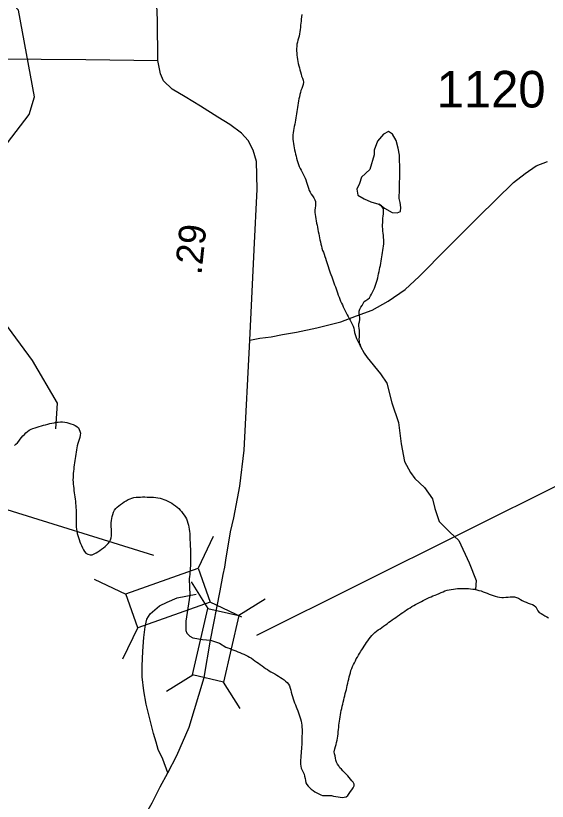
# Model space of a CAD drawing. Extents: x 1950930 to 2061844, y 904556 to 1017002.
# Drawn here: x 1995566 to 1998037, y 913449 to 917098 of the extents above; entities that cross this region are included whole.
import ezdxf

# ---------------------------------------------------------------- set-up
doc = ezdxf.new("R2010")
doc.units = 0
for name, color, linetype in [('Exist Hydrographic Creek Single Shore', 7, 'Continuous'), ('Exist Hydrographic Misc Water Feature', 7, 'Continuous'), ('Exist Road Primary US Structure Standard Bridge CELL', 7, 'Continuous'), ('Exist Road Secondary Structure Standard Bridge CELL', 7, 'Continuous'), ('Exist Road Secondary Structure Standard Bridge Number Label', 7, 'Continuous'), ('Exist Road Secondary Type 51 Attributed', 7, 'Continuous'), ('Exist Road Secondary Type 51 Number Label', 7, 'Continuous')]:
    doc.layers.add(name, color=color, linetype=linetype)

msp = doc.modelspace()

# ---------------------------------------------------------------- linework, layer by layer
at = {"layer": 'Exist Hydrographic Creek Single Shore'}
for points in [[(1995560.5, 915100.6), (1995567.5, 915106.8), (1995574.7, 915114.2), (1995581, 915122.2), (1995587, 915130.2), (1995593.5, 915138.2), (1995600.3, 915145.7), (1995606.7, 915152.9), (1995613.8, 915160.3), (1995621.2, 915166.4), (1995629.4, 915172.1), (1995638.2, 915176.9), (1995646.8, 915180.8), (1995656.7, 915183.7), (1995666.5, 915186.7), (1995676.2, 915190.1), (1995686.2, 915192.3), (1995695.6, 915195.3), (1995705.3, 915197.5), (1995715.3, 915200.9), (1995725, 915203), (1995734.6, 915205.2), (1995744.9, 915207.3), (1995754.9, 915209.1), (1995764.5, 915210.4), (1995774.4, 915210.9), (1995784, 915210.7), (1995794.1, 915209.6), (1995803.9, 915207.6), (1995813.8, 915205), (1995823.4, 915201.9), (1995833, 915198.4), (1995842.1, 915194.5), (1995850.7, 915189.6), (1995858.7, 915183.9)], [(1995858.7, 915183.9), (1995865.2, 915167.9), (1995867.3, 915159), (1995866, 915149.1), (1995864, 915139.2), (1995861.1, 915129.6), (1995858.3, 915119.9), (1995855.2, 915110.1), (1995852.7, 915100), (1995850.7, 915090.5), (1995849, 915080.7), (1995847.4, 915070.8), (1995845.7, 915060.9), (1995844.1, 915051), (1995842.5, 915041.4), (1995840.8, 915031.6), (1995839.6, 915021.6), (1995838, 915011.7), (1995837.1, 915001.3), (1995835.9, 914991.4), (1995834.7, 914981.4), (1995833.9, 914971.8), (1995833, 914961.8), (1995832.8, 914952), (1995832.4, 914942.4), (1995832.8, 914931.7), (1995833.6, 914921.5), (1995834.7, 914912), (1995835.9, 914902.1), (1995837.1, 914892.2), (1995838.6, 914882.2), (1995840.2, 914872.2), (1995841.6, 914862.6), (1995842.9, 914852.7), (1995843.9, 914842.8), (1995844.7, 914832.2), (1995845.5, 914822.2), (1995846, 914812.5), (1995847, 914802.6), (1995847.4, 914792.8), (1995847.4, 914782.7), (1995848, 914772.8), (1995847.8, 914762.3), (1995847.6, 914752.6), (1995847.2, 914742.5), (1995846.8, 914732.8), (1995847.6, 914722.2), (1995848.4, 914712.2), (1995850.3, 914703.1), (1995852.5, 914693.4), (1995855.6, 914683.2), (1995858, 914673.5), (1995861.3, 914664.4), (1995864.8, 914654.6), (1995868.3, 914645.5), (1995872, 914636.5), (1995876.3, 914626.5), (1995881, 914617.2), (1995886.3, 914608.7), (1995892.9, 914602), (1995902.3, 914597), (1995912.4, 914593.8), (1995922.2, 914593.9), (1995931, 914598.2), (1995939.9, 914603), (1995948.3, 914607.8), (1995956.9, 914613.4), (1995965.5, 914619.3), (1995973.9, 914625.8), (1995981.7, 914632.4), (1995989.1, 914638.5), (1995995.8, 914646), (1996002.4, 914654), (1996007.3, 914663), (1996010.6, 914672.6), (1996012, 914681.7), (1996012.5, 914691.8), (1996011.6, 914702.5), (1996011.2, 914712.3), (1996010, 914723), (1996010.4, 914732.7), (1996010.6, 914742.4), (1996011.4, 914752.4), (1996012.9, 914762.4), (1996014.7, 914771.8), (1996017.2, 914781.5), (1996020.7, 914791.6), (1996025.2, 914801.4), (1996031.5, 914808.6), (1996038.5, 914814.9), (1996046.5, 914821.4), (1996054.3, 914827.9), (1996062.5, 914833.9), (1996071.1, 914840), (1996079.7, 914845.1), (1996088.5, 914849.9), (1996097.8, 914853.7), (1996106.8, 914857.3), (1996116, 914859.1), (1996126.3, 914861.6)], [(1996126.3, 914861.6), (1996136.1, 914862.1), (1996146.1, 914861.8), (1996156.6, 914862.6), (1996166.7, 914862.3), (1996176.9, 914862), (1996186.5, 914861.8), (1996197.2, 914861.8), (1996207.3, 914860.7), (1996217.3, 914859.6), (1996227.3, 914858.8), (1996237.2, 914856.9), (1996246.8, 914854.2), (1996255.6, 914850.4), (1996264.9, 914847), (1996273.9, 914842.8), (1996283.3, 914837.7), (1996291.7, 914832.8), (1996300.1, 914827.5), (1996308.5, 914821.7), (1996316.3, 914814.9), (1996324.3, 914808.4), (1996331.3, 914801.6), (1996337.7, 914794.6), (1996344, 914786.2), (1996349.8, 914778.1), (1996355.1, 914769.1), (1996359.6, 914760), (1996363.5, 914750.9), (1996367, 914741), (1996369.7, 914731.7), (1996371.9, 914722), (1996373.3, 914712.8), (1996374.6, 914702.1), (1996375.4, 914692.2), (1996376, 914682.4), (1996376.2, 914671.8), (1996376.4, 914662.1), (1996376.8, 914652.2), (1996377.2, 914642), (1996377.9, 914632.3), (1996378.5, 914621.6), (1996378.7, 914611.7), (1996378.7, 914602), (1996379.1, 914592.3), (1996379.5, 914581.6), (1996379.5, 914571.5), (1996379.7, 914561.7), (1996379.3, 914552.1), (1996378.9, 914541.9), (1996378.1, 914532.3), (1996377.7, 914521.4), (1996376.4, 914511.9), (1996375.2, 914501.9), (1996374, 914492.4), (1996372.7, 914482.5), (1996375.1, 914405.5), (1996357.7, 914285.5), (1996357.7, 914242.9), (1996362.4, 914230.3), (1996376.6, 914216.1), (1996389.3, 914208.2), (1996435, 914200.3), (1996471.8, 914196.7), (1996513.9, 914182.9), (1996543.5, 914165.5)], [(1997333, 914303.1), (1997341.6, 914308.8), (1997349.8, 914314.4), (1997357.6, 914321), (1997366.2, 914326.5), (1997374.8, 914332.2), (1997383, 914337.4), (1997391.4, 914342.2), (1997399.6, 914347.8), (1997408, 914353.5), (1997416.6, 914358.3), (1997425.5, 914363), (1997433.9, 914367.8), (1997443.1, 914372.5), (1997452.1, 914377.3), (1997460.9, 914382), (1997469.8, 914386.7), (1997479, 914390.6), (1997487.8, 914395.3), (1997497.4, 914399.1), (1997506.1, 914403.1), (1997515.7, 914406.9), (1997524.7, 914410), (1997534.3, 914414.3), (1997543.4, 914418.1), (1997552.6, 914422), (1997561.6, 914425.9), (1997571.5, 914428.8), (1997581.3, 914431), (1997590.9, 914432.4), (1997601, 914434.2), (1997610.8, 914435.5), (1997620.5, 914436.8), (1997630.7, 914437.4), (1997641, 914437.4), (1997650.6, 914437.1), (1997661.1, 914437.6), (1997671.1, 914436.8), (1997680.6, 914435.8), (1997690.6, 914434.7), (1997700.6, 914433.6), (1997704.3, 914432.6)], [(1997704.3, 914432.6), (1997710.5, 914430.9), (1997719.7, 914428.2), (1997729.6, 914425.6), (1997739.2, 914422.1), (1997748.4, 914418.6), (1997757.9, 914415.1), (1997767.5, 914411.6), (1997776.7, 914408.2), (1997785.9, 914404.7), (1997795.6, 914401.3), (1997805.4, 914398.6), (1997814.9, 914396.8), (1997825.3, 914395.6), (1997834.5, 914395.4), (1997844.8, 914396.2), (1997855.3, 914396.8), (1997865.1, 914398.1), (1997875.6, 914398.9), (1997885.2, 914397.9), (1997895, 914395.9), (1997903.6, 914391.8), (1997912.7, 914386.8), (1997921.1, 914381.5), (1997929.9, 914376.5), (1997939.1, 914373), (1997948.8, 914369.5), (1997958.4, 914366), (1997968, 914362.5), (1997976.6, 914358.4), (1997984, 914351.5), (1997988.5, 914342.4), (1997993.3, 914333.1), (1998000.2, 914326.4), (1998008.2, 914320.7), (1998016.8, 914315.8), (1998025.7, 914310.3), (1998034.5, 914305.3), (1998043.7, 914301.1)], [(1997074.4, 913468), (1997084.5, 913466.8), (1997093.9, 913467.5), (1997102.3, 913469.8), (1997109.7, 913476), (1997116.5, 913485.1), (1997122.2, 913494), (1997128.8, 913502.7), (1997135.7, 913511.7), (1997140.2, 913520.5), (1997139.4, 913528.7), (1997134.9, 913537.1), (1997129.6, 913544.4), (1997123.4, 913552.2), (1997116.5, 913559.7), (1997109.7, 913567.3), (1997102.5, 913574.9), (1997094.7, 913582.1), (1997087.5, 913589.8), (1997080.4, 913597.4), (1997073.4, 913604.8), (1997067.7, 913613), (1997062.3, 913621.6), (1997058, 913629.9), (1997055.1, 913639.7), (1997052.9, 913649.3), (1997050.6, 913659.5), (1997049, 913669.4), (1997046.3, 913679.2), (1997050.4, 913693.2), (1997053.3, 913702.9), (1997055.8, 913712.7), (1997058.2, 913722.4), (1997060.3, 913732.3), (1997061.9, 913742.1), (1997063.1, 913751.7), (1997064.8, 913761.6), (1997065.6, 913771.7), (1997066.8, 913782.4), (1997067.7, 913792), (1997068.9, 913802), (1997070.1, 913811.5), (1997071.3, 913821.5), (1997072.6, 913831), (1997074.6, 913840.9), (1997076.3, 913850.8), (1997078.3, 913860.6), (1997080, 913870.5), (1997082.4, 913880.2), (1997084.5, 913890.1), (1997086.9, 913899.9), (1997089, 913909.7), (1997091, 913919.5), (1997093.5, 913929.3), (1997095.9, 913939.1), (1997098.4, 913948.8), (1997100.9, 913958.6), (1997103.3, 913967.6), (1997105.8, 913977.3), (1997107.8, 913987.2), (1997110.3, 913997), (1997112.4, 914006.7), (1997114.4, 914016.6), (1997116.9, 914026.4), (1997118.9, 914036.2), (1997122, 914045.9), (1997124.9, 914055.6), (1997128.1, 914065.7), (1997131.8, 914074.4), (1997136.1, 914083.5), (1997140.6, 914092.1), (1997145.2, 914101.3), (1997149.7, 914110.3), (1997154.8, 914118.4), (1997159.7, 914127.4), (1997164.4, 914136), (1997170, 914145.4), (1997175.5, 914153), (1997180.8, 914162), (1997186.4, 914170.1), (1997191.9, 914178.2), (1997197.4, 914186.2), (1997203.6, 914194.6), (1997209.1, 914202.7), (1997215.7, 914210.7), (1997221.6, 914218.7), (1997228.6, 914225.3), (1997236.2, 914232.3), (1997244.2, 914238.8), (1997251.8, 914244.5), (1997260.4, 914249.7), (1997268.6, 914256.2), (1997276.4, 914261.8), (1997284.8, 914268.3), (1997292.4, 914273.6), (1997300.8, 914280.1), (1997308.8, 914285.7), (1997317, 914291.5), (1997325.4, 914297.8), (1997333, 914303.1)], [(1996543.5, 914165.5), (1996552.8, 914162.1), (1996562.6, 914157.8), (1996571.8, 914154.3), (1996581.1, 914150.9), (1996590.1, 914147), (1996599.7, 914143.5), (1996608.9, 914140.5), (1996618, 914135.9), (1996627.6, 914131.6), (1996636.2, 914127.4), (1996645.2, 914123.2), (1996653.7, 914117.9), (1996661.9, 914113), (1996670.5, 914106.8), (1996678.7, 914101.9), (1996687.1, 914095.8), (1996695.3, 914090.1), (1996703.3, 914083.9), (1996711.3, 914078.3), (1996719.7, 914072.6), (1996728.1, 914066.4), (1996736.1, 914061.5), (1996744.5, 914055.4), (1996752.9, 914050.4), (1996761.9, 914045.1), (1996770.7, 914040.1), (1996779.8, 914035), (1996788.6, 914030), (1996797.4, 914023.9), (1996805.4, 914018.9), (1996813.8, 914012.8), (1996820.8, 914006.4), (1996827.9, 914000.5), (1996833.9, 913992.7), (1996838.4, 913984.7), (1996842.3, 913974.8), (1996845, 913965.4), (1996847.4, 913955), (1996849.7, 913944.8), (1996852.8, 913935.1), (1996855.4, 913925.3), (1996859.3, 913915.8), (1996862.8, 913906.4), (1996866.3, 913896.8), (1996870.4, 913887.7), (1996873.9, 913879.1), (1996877.4, 913868.8), (1996880.8, 913859.7), (1996884.5, 913850.7), (1996887.6, 913840.9), (1996890.3, 913831.9), (1996892.9, 913821.8), (1996894.6, 913811.8), (1996896.4, 913802.2), (1996896.4, 913792.5), (1996897.3, 913782.2), (1996897.5, 913772.5), (1996897.5, 913761.9), (1996897, 913752.2), (1996897, 913742), (1996896.2, 913731.7), (1996896.2, 913721.5), (1996895.8, 913711.8), (1996895.4, 913702.1), (1996894.6, 913692.1), (1996893.8, 913681.6), (1996892.9, 913671.7), (1996892.1, 913662.1), (1996891.7, 913651.2), (1996890.9, 913641.5), (1996890.5, 913631.4), (1996890.5, 913621.7), (1996891.1, 913611.9), (1996893.4, 913603), (1996898.7, 913593.7), (1996903.4, 913584.4), (1996906.7, 913575.4), (1996908.9, 913565.8), (1996911.2, 913554.8), (1996913, 913544.9), (1996915.7, 913535.1), (1996920.2, 913526.7), (1996926.2, 913519.2), (1996932.7, 913512.6), (1996940.5, 913505.7), (1996948.7, 913499.2), (1996957.5, 913493), (1996965.9, 913488.1), (1996975, 913483), (1996984, 913478.4), (1996993.2, 913475.8), (1997003.1, 913475.1), (1997013.7, 913475.6), (1997023.4, 913475.2), (1997034, 913475.2), (1997043.9, 913473.4), (1997054.1, 913471.5), (1997064.6, 913469.4), (1997074.4, 913468)]]:
    msp.add_lwpolyline(points, dxfattribs=at)
at = {"layer": 'Exist Hydrographic Misc Water Feature'}
for points in [[(1995753.4, 915179.5), (1995761.3, 915297.4), (1995645.3, 915496.7), (1995470.4, 915730), (1995395.3, 915872.8), (1995245.2, 916036.6), (1995270.2, 916170.7), (1995629.3, 916639.2), (1995654.3, 916720.7), (1995579.2, 917122.6), (1995488.2, 917223), (1995129.4, 917463.3), (1994830.2, 917971.6), (1994630.2, 918205.5), (1994288.2, 918537.4), (1993897.2, 918706.3), (1993755.3, 918732.1), (1993189.1, 918973.6), (1992830.3, 919407.6), (1992706.2, 919830.2), (1992714.2, 919915.4)], [(1996896.2, 917102.8), (1996895.2, 917092.1), (1996894, 917082.1), (1996892.7, 917072.5), (1996891.9, 917062.5), (1996890.7, 917052.9), (1996889.5, 917042.9), (1996888.6, 917033), (1996887.4, 917022.6), (1996885.8, 917012.7), (1996884.1, 917002.9), (1996881.7, 916993), (1996878.4, 916984.2), (1996875.9, 916974.5), (1996873.9, 916964.6), (1996872.6, 916954.7), (1996872.4, 916944.9), (1996872.2, 916934), (1996872.6, 916924.2), (1996873.7, 916914.3), (1996874.1, 916904.5), (1996876.3, 916894.8), (1996877.6, 916884.9), (1996879.8, 916874.8), (1996882.5, 916865.1), (1996885.2, 916855.7), (1996887.8, 916846), (1996890.5, 916836.3), (1996892.9, 916826.1), (1996895.6, 916817.2), (1996899.1, 916807.3), (1996903, 916797.4), (1996904.4, 916788.3), (1996902.8, 916778.4), (1996900.1, 916769.5), (1996896, 916760), (1996892.1, 916749.9), (1996889.5, 916741.1), (1996887, 916731.3), (1996884.9, 916721.4), (1996882.7, 916711.6), (1996881.1, 916701.7), (1996879.4, 916691.8), (1996877.4, 916682.1), (1996876.1, 916671.7), (1996874.5, 916661.8), (1996872.9, 916651.9), (1996871.2, 916642), (1996869.6, 916632.4), (1996867.9, 916622.6)], [(1996867.9, 916622.6), (1996866.7, 916612.6), (1996865.5, 916602.7), (1996863.8, 916593.2), (1996861.4, 916583.4), (1996859.3, 916573.6), (1996857.3, 916563.7), (1996855.6, 916553.8), (1996854.4, 916543.9), (1996854.4, 916533.3), (1996855.2, 916523.4), (1996855.8, 916513.6), (1996857.5, 916503.7), (1996858.7, 916493.7), (1996861, 916484), (1996862.8, 916474), (1996864.9, 916464.4), (1996867.1, 916454.2), (1996869.4, 916445.4), (1996872, 916435.3), (1996874.7, 916425.5), (1996877.8, 916416.1), (1996881.3, 916406.3), (1996884.7, 916397.2), (1996889.3, 916388.4), (1996893.8, 916380), (1996898.7, 916370.8), (1996903.4, 916361.5), (1996907.9, 916352.7), (1996911.6, 916343.6), (1996915.1, 916334.6), (1996918.2, 916324.3), (1996920.8, 916315.4), (1996923.9, 916305.7), (1996927, 916296.3), (1996930.5, 916286.4), (1996935, 916277.2), (1996939.9, 916269.1), (1996945.6, 916260.6), (1996951.6, 916252.4), (1996956.5, 916243), (1996959.6, 916234), (1996960, 916224.3), (1996959.8, 916214.5), (1996958.6, 916204.6), (1996957.1, 916194.2), (1996957.1, 916184.1), (1996958.6, 916174.1), (1996959.8, 916164.2), (1996961.2, 916154.7), (1996962.9, 916144.7), (1996965.1, 916134.6), (1996967, 916125), (1996969, 916115), (1996971.3, 916105.2), (1996972.5, 916095.3), (1996975.2, 916085.2), (1996976.6, 916075.6), (1996978.9, 916066.4), (1996980.5, 916056.3), (1996983.2, 916046.6), (1996985.2, 916036.6), (1996987.5, 916026.9), (1996989.7, 916017.6), (1996993.2, 916007.7), (1996997.3, 915998.6), (1997000.8, 915989.6), (1997003.9, 915979.8), (1997007.2, 915970.7), (1997009.6, 915960.7), (1997013.1, 915950.7), (1997015.8, 915941.8), (1997018.8, 915932.1), (1997021.9, 915922.6), (1997025.4, 915912.8), (1997028.7, 915903.8), (1997031.8, 915894.8), (1997035.3, 915884.9), (1997038.9, 915875.9), (1997042.2, 915865.5), (1997045.9, 915856.5), (1997049, 915847.5), (1997052.5, 915837.7), (1997056, 915828.6), (1997059.2, 915819.2), (1997062.7, 915809.8), (1997065.8, 915800.3), (1997069.7, 915790.4), (1997072.8, 915781.4), (1997076.9, 915772.2), (1997080.4, 915763.2), (1997084.9, 915754), (1997088.8, 915744.9), (1997093.3, 915735.6), (1997097.8, 915726.9), (1997102.1, 915717.7), (1997106.6, 915708.5), (1997111.1, 915700.1), (1997116.5, 915691.1), (1997121.4, 915682.7)], [(1997255.1, 916221.6), (1997266.3, 916213.9), (1997280.9, 916203.9), (1997317, 916183.4), (1997338.9, 916182.1), (1997354.7, 916188.2), (1997357, 916206.5), (1997352.9, 916230.3), (1997348.6, 916248.4), (1997350.4, 916291.5), (1997351.6, 916376.1), (1997350.8, 916450.1), (1997344.7, 916482.3), (1997334.4, 916517.6), (1997318.2, 916547.6), (1997298.5, 916559.5), (1997276.2, 916547.5), (1997248.7, 916515.2), (1997233.1, 916472.9), (1997232.9, 916451.1), (1997211.8, 916383.2), (1997173.9, 916347.2), (1997164, 916318.6), (1997152.5, 916292.5), (1997156.2, 916264.7), (1997186.6, 916246.6), (1997216.9, 916233.1), (1997255.1, 916221.6)], [(1997169.2, 915561.4), (1997168.1, 915568.3), (1997165, 915572.8), (1997164.2, 915585.6), (1997163.4, 915596), (1997164.4, 915606.4), (1997164.2, 915616.1), (1997164.2, 915625.8), (1997163.8, 915636.1), (1997162.4, 915646), (1997161.6, 915655.5), (1997162, 915666.3), (1997164, 915676.2), (1997165.3, 915685.8), (1997165.3, 915696), (1997164, 915705.9), (1997163, 915715.3), (1997163, 915725.5), (1997166.3, 915735.1), (1997171.4, 915743.2), (1997176.3, 915752.2), (1997181.3, 915761.3), (1997186.6, 915769.8), (1997194.2, 915775.5), (1997202.8, 915781.2), (1997210.4, 915787.7), (1997215.9, 915795.8), (1997220.8, 915804.7), (1997225.1, 915813.5), (1997229.6, 915822.5), (1997233.7, 915832), (1997237.4, 915841.2), (1997240.7, 915850.9), (1997244, 915860.1), (1997246.5, 915869.8), (1997249.3, 915879.6), (1997251.4, 915889.4), (1997253.4, 915899.3), (1997255.5, 915909), (1997257.7, 915918.9), (1997259.6, 915928.3), (1997261.6, 915938.1), (1997263.3, 915948.1), (1997264.9, 915957.9), (1997266.6, 915967.9), (1997268.2, 915977.3), (1997269.8, 915987.2), (1997271.9, 915997.1), (1997273.1, 916007), (1997275, 916017.7), (1997276.2, 916027.2), (1997277, 916037.3), (1997277.2, 916047), (1997277.2, 916057.2), (1997276.8, 916066.9), (1997276.4, 916076.7), (1997275.2, 916087.5), (1997273.7, 916097.5), (1997272.9, 916106.9), (1997271.9, 916116.8), (1997271.9, 916127), (1997272.7, 916136.5), (1997273.5, 916146.6), (1997273.5, 916157.1), (1997274.8, 916167.1), (1997276, 916177.4), (1997276.8, 916187.5), (1997276, 916197.3), (1997272.7, 916205.5), (1997266.3, 916213.9), (1997255.1, 916221.6)], [(1997121.4, 915682.7), (1997126.5, 915674.6), (1997130.8, 915665.4), (1997134.9, 915656.3), (1997137.4, 915646.1), (1997139.2, 915636.6), (1997140.9, 915626.6), (1997144.5, 915617.5), (1997148, 915607.7), (1997151.1, 915598.7), (1997155.6, 915589.4), (1997160.3, 915579.4), (1997165, 915572.8), (1997168.1, 915568.3), (1997169.2, 915561.4)], [(1997169.2, 915561.4), (1997186, 915529.7), (1997200.5, 915510.4), (1997261.4, 915434.5), (1997291.8, 915391.4), (1997314.5, 915299.1), (1997345.5, 915208.8), (1997358.2, 915109.4), (1997373, 915027.6), (1997401.3, 914975.4), (1997421.4, 914948), (1997465.9, 914906), (1997504.4, 914854.2), (1997514.5, 914808.5), (1997535.2, 914748.9), (1997583.6, 914699.3), (1997625.8, 914660), (1997674.8, 914556.4), (1997707.4, 914474.4), (1997704.3, 914432.6)]]:
    msp.add_lwpolyline(points, dxfattribs=at)
at = {"layer": 'Exist Road Secondary Structure Standard Bridge CELL'}
for p, q in [((1996485, 914678.4), (1996414.8, 914531.2)), ((1996079.2, 914409.2), (1995932.1, 914479.4)), ((1996382.4, 914467.6), (1996459.1, 914344.7)), ((1996726.4, 914387.9), (1996603.5, 914311.2)), ((1996617.7, 914303.8), (1996470.5, 914374)), ((1996133.6, 914255.5), (1996063.5, 914108.4)), ((1996390.1, 914034.9), (1996267.2, 913958.2)), ((1996531.2, 914002.2), (1996607.9, 913879.3))]:
    msp.add_line(p, q, dxfattribs=at)
for points in [[(1996470.5, 914374), (1996133.9, 914254.8), (1996078.2, 914412), (1996414.8, 914531.2)], [(1996603.5, 914311.2), (1996531.9, 914002.1), (1996387.5, 914035.5), (1996459.1, 914344.7)]]:
    msp.add_lwpolyline(points, close=True, dxfattribs=at)
at = {"layer": 'Exist Road Secondary Structure Standard Bridge Number Label'}
for p, q in [((1996208.2, 914590.2), (1993734.4, 915362.1)), ((1996687, 914220), (1998176.9, 914962.3))]:
    msp.add_line(p, q, dxfattribs=at)
at = {"layer": 'Exist Road Secondary Type 51 Attributed'}
for points in [[(1996227.7, 916889.9), (1996225.1, 917077.4), (1996215.3, 917320.7)], [(1995474.9, 916896.8), (1995893, 916894.9), (1996227.7, 916889.9)], [(1996654.6, 915590.1), (1996675.6, 916010.6), (1996688.6, 916291.3), (1996685.4, 916419.7), (1996670.4, 916473.6), (1996647.6, 916518.1), (1996616.6, 916552.3), (1996561.7, 916592.7), (1996506.5, 916626.1), (1996426.1, 916677.6), (1996353.9, 916721.2), (1996294, 916756.3), (1996253.3, 916795.1), (1996239.1, 916827.8), (1996227.7, 916889.9)], [(1996654.6, 915590.1), (1996700.5, 915599.7), (1996754.3, 915606.8), (1996805.9, 915616.3), (1996870.9, 915628.4), (1996966.6, 915647.5), (1997077.5, 915676.2), (1997150.3, 915703), (1997223, 915729.8), (1997297, 915772.2), (1997377, 915826.5), (1997442.1, 915885.8), (1997572.2, 916017.8), (1997717.7, 916163.3), (1997880, 916322.9), (1997933.8, 916365.3), (1997985.6, 916399.6), (1998037.6, 916419.8)], [(1996471.8, 914196.7), (1996517.1, 914426.3), (1996530.5, 914502.9), (1996538.7, 914535.6), (1996543.3, 914569), (1996564.6, 914700.6), (1996580.2, 914764.7), (1996597.9, 914854.7), (1996608.6, 914912.4), (1996629.1, 915080.3), (1996654.6, 915590.1)], [(1996273.8, 913580.5), (1996251, 913644.3), (1996228.2, 913689.9), (1996219.1, 913723.4), (1996207.7, 913763.6), (1996172.8, 913900.4), (1996162.2, 913961.2), (1996153.9, 914027.3), (1996153.9, 914075.9), (1996156.9, 914145.8), (1996161.4, 914209.6), (1996169, 914259.8), (1996176.6, 914294.7), (1996191.7, 914320), (1996235.1, 914356.3), (1996270, 914374.5), (1996316.8, 914394.5), (1996404.8, 914410.6)], [(1996273.8, 913580.5), (1996314.8, 913661.1), (1996373.2, 913792.5), (1996443.1, 914023.5), (1996471.8, 914196.7)], [(1995191.3, 911985), (1995239.9, 912027.5), (1995321.1, 912093.6), (1995410.7, 912163.5), (1995463.8, 912212.2), (1995507.8, 912239.5), (1995556.4, 912285.1), (1995609.6, 912330.7), (1995659.7, 912397.5), (1995700.6, 912462.9), (1995720.4, 912499.3), (1995744.7, 912541.9), (1995786.4, 912633.8), (1995844.1, 912752.4), (1996028.6, 913087.4), (1996122.7, 913291), (1996165.2, 913379.2), (1996200.2, 913441.5), (1996238.1, 913515.9), (1996273.8, 913580.5)]]:
    msp.add_lwpolyline(points, dxfattribs=at)

# ---------------------------------------------------------------- texts
at = {"layer": 'Exist Road Primary US Structure Standard Bridge CELL'}
msp.add_text('.29', height=125, rotation=83.9421, dxfattribs=at).set_placement((1996429.4, 915891))
at = {"layer": 'Exist Road Secondary Type 51 Number Label'}
msp.add_text('1120', height=170, dxfattribs=at).set_placement((1997523.5, 916671.2))

doc.saveas('drawing.dxf')
